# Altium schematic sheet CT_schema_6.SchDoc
size 297 x 271 mm
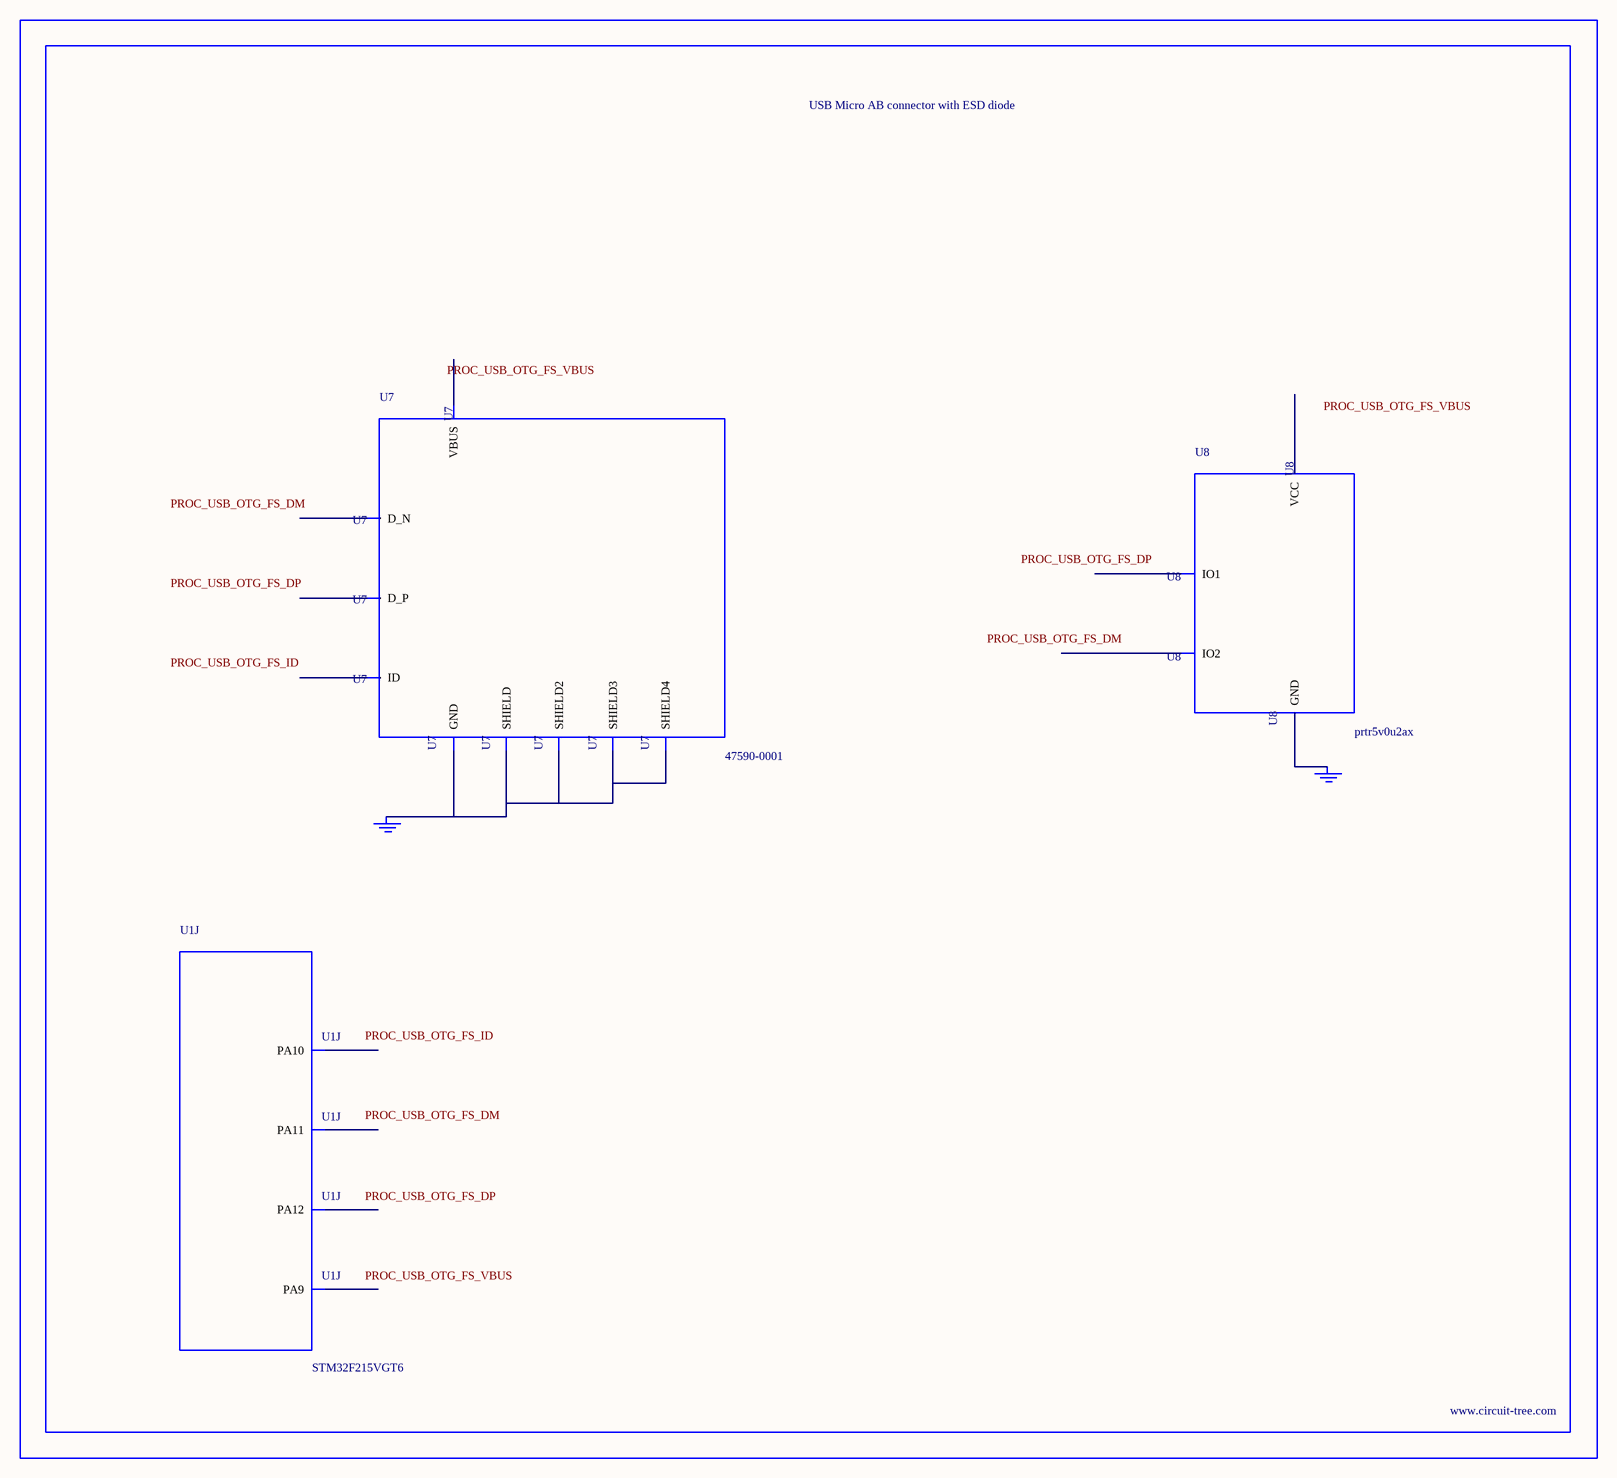
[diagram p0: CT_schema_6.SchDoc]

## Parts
BORDER5  (no value)
GND_INSTANCE_5_0  (no value)
GND_INSTANCE_5_1  (no value)
U1  STM32F215VGT6  [LQFP100]  (part J of 10)
U7  47590-0001  [MICRO_USB_AB]
U8  prtr5v0u2ax  [SOT143B]

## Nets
NetGND_INSTANCE_5_0_0: GND_INSTANCE_5_0.0(GND) U7.5(GND) U7.6(SHIELD) U7.7(SHIELD2) U7.8(SHIELD3) U7.9(SHIELD4)
NetGND_INSTANCE_5_1_0: GND_INSTANCE_5_1.0(GND) U8.1(GND)

Not connected (* = marked no-connect by the designer): U1 68(PA9) 69(PA10) 70(PA11) 71(PA12); U7 1(VBUS) 2(D_N) 3(D_P) 4(ID); U8 2(IO1) 3(IO2) 4(VCC)

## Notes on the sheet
- Labels drawn without touching a wire or pin: PROC_USB_OTG_FS_DM, PROC_USB_OTG_FS_DP, PROC_USB_OTG_FS_ID, PROC_USB_OTG_FS_VBUS

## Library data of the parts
BORDER5 = BORDER_PAGE5
GND_INSTANCE_5_0 GND_INSTANCE_5_1 = GND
